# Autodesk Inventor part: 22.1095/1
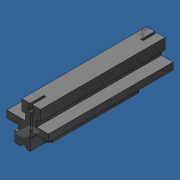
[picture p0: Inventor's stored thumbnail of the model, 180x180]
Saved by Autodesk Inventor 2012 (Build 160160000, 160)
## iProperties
Created: 2007-06
Part Number: 22.1095/1
Material: UHMW, Black
Document SubType Name: Modeling
Designer: Andy Moles
Density: 0.94 g/cm^3
Description: MACHINE TO 22.1095/1
Stock Number: 22.1087 DOUBLE SLIDE BAR
Mass: 35.3504 g
Surface Area: 142.91 cm^2
Volume: 37.6069 cm^3
Vendor: F
Author: Andy Moles
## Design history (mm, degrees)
sketch "Sketch1"
  geometry: L1 (4.1, 0)-(4.1, -4.7); L2 (17.5, 0)-(4.1, 0) reference; L3 (17.5, 5)-(17.5, 0) reference; L4 (9.1, 5)-(17.5, 5) reference; L5 (9.1, 9.7)-(9.1, 5); L6 (11.75, 9.7)-(9.1, 9.7); L7 (11.75, 17.5)-(11.75, 9.7); L8 (-1.75, 17.5)-(11.75, 17.5); L9 (-1.75, 9.7)-(-1.75, 17.5); L10 (0.9, 9.7)-(-1.75, 9.7); L11 (0.9, 5)-(0.9, 9.7); L12 (-12.5, 5)-(0.9, 5) reference; L13 (-12.5, 0)-(-12.5, 5) reference; L14 (-4.1, 0)-(-12.5, 0) reference; L15 (-4.1, -4.7)-(-4.1, 0); L16 (-6.75, -4.7)-(-4.1, -4.7); L17 (-6.75, -12.5)-(-6.75, -4.7); L18 (6.75, -4.7)-(6.75, -12.5); L19 (4.1, -4.7)-(6.75, -4.7); L20 (-2.5, -12.5)-(0, -10); L21 (0, -10)-(2.5, -12.5); L22 (6.75, -12.5)-(2.5, -12.5); L23 (-2.5, -12.5)-(-6.75, -12.5); 4 further points
  constraints: 46 end point, 8 vertical, 7 horizontal, 5 equal length, 2 horizontal alignment, 2 vertical alignment, 1 midpoint, 1 other
  dimensions: "d1" = 90 deg angle of L21 L20; "d21" = 13.5 distance of L8.start L7.start; "d22" = 2.5 distance from line of L22 L20.end; "d23" = 8.20001 distance between parallel lines of L5 L11; "d24" = 8.20001 distance between parallel lines of L1 L15; "d25" = 1.75 distance from line of L9 point (0, 0); "d26" = 4.10001 distance from line of point (0, 0) L1; "d27" = 6.75 distance from line of point (0, 0) L18; "d28" = 0.89999 distance from line of L11 point (0, 0); "d29" = 4.7 distance between parallel lines of L12 L10; "d30" = 4.7 distance between parallel lines of L16 L14; "d32" = 30 distance between parallel lines of L23 L8
extrude "Extrusion1" new body sketch "Sketch1" stored distance "d2" = 90; taper "d3" = 0 deg
sketch "Sketch2"
  geometry: L1 (4.25, 0)-(0, 0) reference; L2 (4.25, -90)-(4.25, 0) reference; L3 (1.75, -9.67)-(1.75, 0); L4 (-9.25, -90)-(-9.25, 0) reference; A1 r 5 centre (6.75, -9.67) between (1.75, -9.67) and (4.25, -14); 1 further point
  constraints: 2 end point, 2 point on circle, 2 point on line, 1 centre point, 1 parallel, 1 tangent
  dimensions: "d4" = 10 diameter of A1; "d5" = 11 distance between parallel lines of L3 L4; "d6" = 14 distance from line of A1.end L1
extrude "Extrusion2" cut sketch "Sketch2" distance "d7" = 12; taper "d8" = 0 deg
sketch "Sketch3"
  geometry: L1 (-1.75, 17.5)-(11.75, 17.5) reference; L2 (-1.75, 9.7)-(-1.75, 17.5) reference; L3 (4.25, -12.5)-(2.5, -12.5) reference; L4 (4.25, -3.157)-(5.75, -3.157); L5 (4.145, 17.5)-(4.145, 15.714); L6 (4.25, 11.446)-(4.25, -3.157); L7 (5.75, -3.157)-(5.75, 11.446); L8 (5.855, 15.714)-(5.855, 17.5); L9 (4.145, 17.5)-(5.855, 17.5); A1 r 2.281 centre (5, 13.6) between (4.145, 15.714) and (4.25, 11.446); A2 r 2.281 centre (5, 13.6) between (5.75, 11.446) and (5.855, 15.714); 6 further points
  constraints: 12 end point, 5 midpoint, 4 parallel, 4 perpendicular, 4 point on circle, 3 vertical alignment, 2 centre point, 2 point on line, 1 collinear, 1 horizontal alignment
  dimensions: "d9" = 1.5 distance of L4.start L4.end
extrude "Extrusion3" cut sketch "Sketch3" distance "d11" = 10; taper "d12" = 0 deg
mirror "Mirror1"
thread "Thread5" dims "d33" = 10, "d34" = 0
thread "Thread6" dims "d35" = 10, "d36" = 0
thread "Thread7" dims "d37" = 10, "d38" = 0
thread "Thread8" dims "d39" = 10, "d40" = 0
body "Solid1"
other parameters: "d0" = 2.5, "d10" = 4
